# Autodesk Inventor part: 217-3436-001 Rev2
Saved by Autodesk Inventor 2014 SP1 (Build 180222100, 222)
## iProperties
Created: 2014-06
Part Number: 217-3436-001 Rev2
Material: Aluminum 6061
Document SubType Name: Modeling
Designer: Michael
Density: 2.71 g/cm^3
Appearance: Aluminum - Flat
Author: Michael
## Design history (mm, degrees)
node "217-3436-001 Rev2.ipt1"
node "Chamfer1"
node "Base1"
